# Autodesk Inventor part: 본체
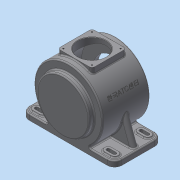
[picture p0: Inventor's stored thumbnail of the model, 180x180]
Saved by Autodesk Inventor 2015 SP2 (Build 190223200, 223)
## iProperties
Created: 2015-06
Part Number: 본체
Material: 일반
Document SubType Name: Modeling
Designer: AMC
Density: 1 g/cm^3
Appearance: 기본값
Author: AMC
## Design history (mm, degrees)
sketch "스케치1"
  geometry: L1 (-115, 59)-(115, 59); L2 (115, 59)-(115, -59); L3 (115, -59)-(-115, -59); L4 (-115, -59)-(-115, 59); 3 further points
  constraints: 8 end point, 2 midpoint, 2 parallel, 1 horizontal, 1 horizontal alignment, 1 perpendicular, 1 vertical alignment
  dimensions: "d0" = 230 distance of L1.start L1.end; "d1" = 118 distance of L1.end L2.end
extrude "돌출1" new body sketch "스케치1" distance "d2" = 14; taper "d3" = 0 deg
sketch "스케치2"
  geometry: L1 (-97, -59)-(97, -59) reference; L2 (97, 59)-(-97, 59) reference; L3 (97, 50)-(81, 50); L4 (81, 32)-(97, 32); A1 r 9 centre (97, 41) between (97, 32) and (97, 50); A2 r 9 centre (81, 41) between (81, 50) and (81, 32); 1 further point
  constraints: 5 point on circle, 4 end point, 4 tangent, 2 centre point, 2 horizontal, 1 point on line
  dimensions: "d11" = 9 radius of A2; "d12" = 16 distance of A1.centre A2.centre; "d13" = 97 horizontal distance of point (0, 0) A1.centre; "d14" = 41 vertical distance of point (0, 0) A2.centre
extrude "돌출2" join sketch "스케치2" distance "d15" = 3; taper "d16" = 0 deg
sketch "스케치3"
  geometry: L1 (81, 32)-(97, 32) reference; L2 (97, 50)-(81, 50) reference; L3 (81, 45)-(97, 45); L4 (81, 37)-(97, 37); A1 r 9 centre (81, 41) between (81, 50) and (81, 32) reference; A2 r 9 centre (97, 41) between (97, 32) and (97, 50) reference; A3 r 4 centre (81, 41) between (81, 45) and (81, 37); A4 r 4 centre (97, 41) between (97, 37) and (97, 45); 1 further point
  constraints: 4 end point, 4 point on circle, 3 tangent, 2 centre point, 2 coincident, 1 equal radius
  dimensions: "d17" = 8 distance between parallel lines of L4 L3
extrude "돌출3" cut sketch "스케치3" stored distance "d18" = 3; taper "d19" = 0 deg
sketch "스케치4"
  geometry: L1 (115, 14)-(115, 0) reference; L2 (115, 0)-(-115, 0) reference; L3 (-115, 0)-(-115, 14) reference; L4 (-115, 14)-(115, 14) reference; C1 r 85 at (0, 85); 1 further point
  constraints: 1 centre point
  dimensions: "d21" = 170 diameter of C1; "d22" = 170 dimension on C1 L2
extrude "돌출4" join sketch "스케치4" stored distance "d23" = 118; taper "d24" = 0 deg
fillet "모깎기5" dims "d26" = 18
fillet "모깎기6" dims "d27" = 3
fillet "모깎기7" dims "d28" = 3
fillet "모깎기8" dims "d29" = 3
node "작업 평면1"
sketch "스케치5"
  geometry: L1 (-42.5, -42.5)-(42.5, -42.5); L2 (42.5, -42.5)-(42.5, 42.5); L3 (42.5, 42.5)-(-42.5, 42.5); L4 (-42.5, 42.5)-(-42.5, -42.5); 3 further points
  constraints: 8 end point, 2 midpoint, 2 parallel, 2 perpendicular, 1 horizontal, 1 horizontal alignment, 1 vertical alignment
  dimensions: "d31" = 85 distance of L3.end L1.start
extrude "돌출5" join sketch "스케치5" stored distance "d32" = 118; taper "d33" = 0 deg
fillet "모깎기9" dims "d34" = 7
fillet "모깎기10" dims "d35" = 3
sketch "스케치6"
  geometry: L1 (35.5, -35.5)-(-35.5, -35.5); L2 (-35.5, -35.5)-(-35.5, 35.5); L3 (-35.5, 35.5)-(35.5, 35.5); L4 (35.5, 35.5)-(35.5, -35.5); L5 (35.5, -35.5)-(-35.5, 35.5); L6 (-35.5, -35.5)-(35.5, 35.5); 5 further points
  constraints: 12 end point, 4 coincident, 2 midpoint, 2 parallel, 1 horizontal, 1 perpendicular
  dimensions: "d36" = 71 distance of L1.end L2.end; "d37" = 71 distance of L2.end L3.end
hole "구멍1" sketch "스케치6" at (-35.5, -35.5), (-35.5, 35.5), (35.5, 35.5), (35.5, -35.5) diameter "d38" = 3.242; stored, may be unused: countersink angle "d42" = 90 deg, drill point angle "d44" = 118 deg; dims "d39" = 10, "d40" = 4, "d41" = 2, "d43" = 13
sketch "스케치7"
  geometry: L1 (55.857, 14)-(112, 14) reference; L2 (115, 11)-(115, 0) reference; L3 (115, 0)-(-115, 0) reference; L4 (-115, 0)-(-115, 11) reference; L5 (-112, 14)-(-55.857, 14) reference; L6 (-42.5, 160.324)-(-42.5, 173) reference; L7 (-42.5, 173)-(42.5, 173) reference; L8 (42.5, 173)-(42.5, 160.324) reference; C1 r 77 at (0, 85); A1 r 3 centre (112, 11) between (115, 11) and (112, 14) reference; A2 r 3 centre (-112, 11) between (-112, 14) and (-115, 11) reference; A3 r 3 centre (-55.857, 17) between (-55.857, 14) and (-53.953, 19.318) reference; A4 r 85 centre (0, 85) between (-43.949, 157.756) and (-53.953, 19.318) reference; A5 r 3 centre (-45.5, 160.324) between (-43.949, 157.756) and (-42.5, 160.324) reference; A6 r 3 centre (45.5, 160.324) between (42.5, 160.324) and (43.949, 157.756) reference; A7 r 85 centre (0, 85) between (53.953, 19.318) and (43.949, 157.756) reference; A8 r 3 centre (55.857, 17) between (53.953, 19.318) and (55.857, 14) reference; 1 further point
  constraints: 1 centre point, 1 coincident
  dimensions: "d45" = 154 diameter of C1
extrude "돌출6" cut sketch "스케치7" stored distance "d46" = 102; taper "d47" = 0 deg
sketch "스케치8"
  geometry: L1 (41.143, -11)-(0, -11) reference; L2 (0, 0)-(0, -11) reference; L3 (0, 0)-(194, 0) reference; L4 (194, 0)-(194, -11) reference; L5 (194, -11)-(152.857, -11) reference; C1 r 65 at (97, -85); A1 r 6 centre (152.857, -17) between (152.857, -11) and (149.049, -21.636) reference; A2 r 82 centre (97, -85) between (44.951, -21.636) and (149.049, -21.636) reference; A3 r 6 centre (41.143, -17) between (44.951, -21.636) and (41.143, -11) reference; 1 further point
  constraints: 1 centre point, 1 coincident
  dimensions: "d48" = 130 diameter of C1
extrude "돌출7" join sketch "스케치8" distance "d49" = 3; taper "d50" = 0 deg
fillet "모깎기11" dims "d51" = 3
sketch "스케치9"
  geometry: C1 r 65 at (0, 0) reference; C2 r 47.5 at (0, 0); 1 further point
  constraints: 1 centre point, 1 coincident
  dimensions: "d52" = 95 diameter of C2
extrude "돌출8" cut sketch "스케치9" stored distance "d53" = 3; taper "d54" = 0 deg
sketch "스케치10"
  geometry: C1 r 47.5 at (0, 0) reference; C2 r 65 at (0, 0) reference; 2 further points
  constraints: 1 horizontal alignment
  dimensions: "d55" = 55 distance of C1.centre point (55, 0)
hole "구멍2" sketch "스케치10" at (55, 0) diameter "d56" = 3.242; stored, may be unused: countersink angle "d60" = 90 deg, drill point angle "d62" = 118 deg; dims "d57" = 10, "d58" = 4, "d59" = 2, "d61" = 13
sketch "스케치11"
  geometry: L1 (152.857, 11)-(194, 11) reference; L2 (194, 0)-(194, 11) reference; L3 (194, 0)-(0, 0) reference; L4 (0, 0)-(0, 11) reference; L5 (0, 11)-(41.143, 11) reference; C1 r 65 at (97, 85); A1 r 6 centre (41.143, 17) between (41.143, 11) and (44.951, 21.636) reference; A2 r 82 centre (97, 85) between (149.049, 21.636) and (44.951, 21.636) reference; A3 r 6 centre (152.857, 17) between (149.049, 21.636) and (152.857, 11) reference; 1 further point
  constraints: 1 centre point, 1 coincident
  dimensions: "d66" = 130 diameter of C1
extrude "돌출9" join sketch "스케치11" distance "d67" = 13; taper "d68" = 0 deg
fillet "모깎기12" dims "d69" = 3
sketch "스케치12"
  geometry: L1 (-81, 70.236)-(-97, 70.236) reference; L2 (-103.633, 71)-(-108.18, 71) reference; L3 (-111.967, 74)-(-111.967, 85) reference; L4 (-111.967, 85)-(111.967, 85) reference; L5 (111.967, 85)-(111.967, 74) reference; L6 (108.18, 71)-(103.633, 71) reference; L7 (97, 70.236)-(81, 70.236) reference; L8 (74.367, 71)-(55.857, 71) reference; L9 (-55.857, 71)-(-74.367, 71) reference; C1 r 77 at (0, 0) reference; C2 r 31 at (0, 0); A1 r 3 centre (55.857, 68) between (55.857, 71) and (53.953, 65.682) reference; A2 r 85 centre (0, 0) between (-53.953, 65.682) and (53.953, 65.682) reference; A3 r 3 centre (-55.857, 68) between (-53.953, 65.682) and (-55.857, 71) reference; 1 further point
  constraints: 1 centre point, 1 coincident, 6 other
  dimensions: "d70" = 62 diameter of C2
extrude "돌출10" join sketch "스케치12" distance "d71" = 3.5; taper "d72" = -25 deg
fillet "모깎기13" dims "d73" = 3
hole "구멍3" diameter "d76" = 30; stored, may be unused: countersink angle "d80" = 90 deg, drill point angle "d82" = 0 deg; dims "d74" = 10, "d75" = 10, "d77" = 10, "d78" = 47, "d79" = 14, "d81" = 17
fillet "모깎기14" dims "d83" = 3
fillet "모깎기15" dims "d84" = 0.3
chamfer "모따기1" distance "d85" = 1; stored, may be unused: second distance "d86" = 2, angle "d87" = 45 deg
sketch "스케치13"
  geometry: C1 r 35 at (0, 0); 1 further point
  constraints: 1 centre point, 1 coincident
  dimensions: "d88" = 70 diameter of C1
extrude "돌출11" cut sketch "스케치13" stored distance "d89" = 3.5; taper "d90" = 0 deg
chamfer "모따기2" distance "d91" = 1; stored, may be unused: second distance "d92" = 2, angle "d93" = 45 deg
sketch "스케치14"
  geometry: L1 (55.857, 14)-(112, 14) reference; L2 (115, 11)-(115, 0) reference; L3 (115, 0)-(-115, 0) reference; L4 (-115, 0)-(-115, 11) reference; L5 (-112, 14)-(-55.857, 14) reference; L6 (-42.5, 160.324)-(-42.5, 173) reference; L7 (-42.5, 173)-(-36, 173) reference; L8 (-36, 173)-(-35, 172) reference; L9 (-35, 172)-(-35, 153.586) reference; L10 (35, 153.586)-(35, 172) reference; L11 (35, 172)-(36, 173) reference; L12 (36, 173)-(42.5, 173) reference; L13 (42.5, 173)-(42.5, 160.324) reference; L14 (109, 14)-(97, 14) reference; L15 (109, 14)-(84.87, 80.297); A1 r 3 centre (112, 11) between (115, 11) and (112, 14) reference; A2 r 3 centre (-112, 11) between (-112, 14) and (-115, 11) reference; A3 r 3 centre (-55.857, 17) between (-55.857, 14) and (-53.953, 19.318) reference; A4 r 85 centre (0, 85) between (-43.949, 157.756) and (-53.953, 19.318) reference; A5 r 3 centre (-45.5, 160.324) between (-43.949, 157.756) and (-42.5, 160.324) reference; A6 r 77 centre (0, 85) between (-35, 153.586) and (35, 153.586) reference; A7 r 3 centre (45.5, 160.324) between (42.5, 160.324) and (43.949, 157.756) reference; A8 r 85 centre (0, 85) between (53.953, 19.318) and (43.949, 157.756) reference; A9 r 3 centre (55.857, 17) between (53.953, 19.318) and (55.857, 14) reference; 1 further point
  constraints: 2 end point, 1 point on circle, 1 point on line
  dimensions: "d94" = 6 distance from line of L2 L15.start; "d95" = 110 deg angle of L3 L15
extrude "돌출12" join sketch "스케치14" stored distance "d96" = 15; taper "d97" = 0 deg
fillet "모깎기16" dims "d98" = 7.5
fillet "모깎기17" dims "d99" = 3
fillet "모깎기18" dims "d100" = 7.5
fillet "모깎기19" dims "d101" = 3
node "작업 평면3"
  node "작업 평면2"
sketch "스케치15"
  geometry: 2 further points
  constraints: 1 vertical alignment, 1 other
extrude "돌출13" join sketch "스케치15" distance "d103" = 0.5; taper "d104" = 0 deg
node "솔리드1"
mirror "대칭1"
mirror "대칭2"
pattern_circular "원형 패턴1" dims angle "d64" = 360 deg
mirror "대칭3"
node "절단 모서리 투영1"
node "절단 모서리 투영2"
node "절단 모서리 투영3"
node "절단 모서리 투영4"
node "절단 모서리 투영5"
node "절단 모서리 투영6"
node "절단 모서리 투영7"
node "절단 모서리 투영8"
other parameters: "d30" = -173, "d102" = 25 deg
